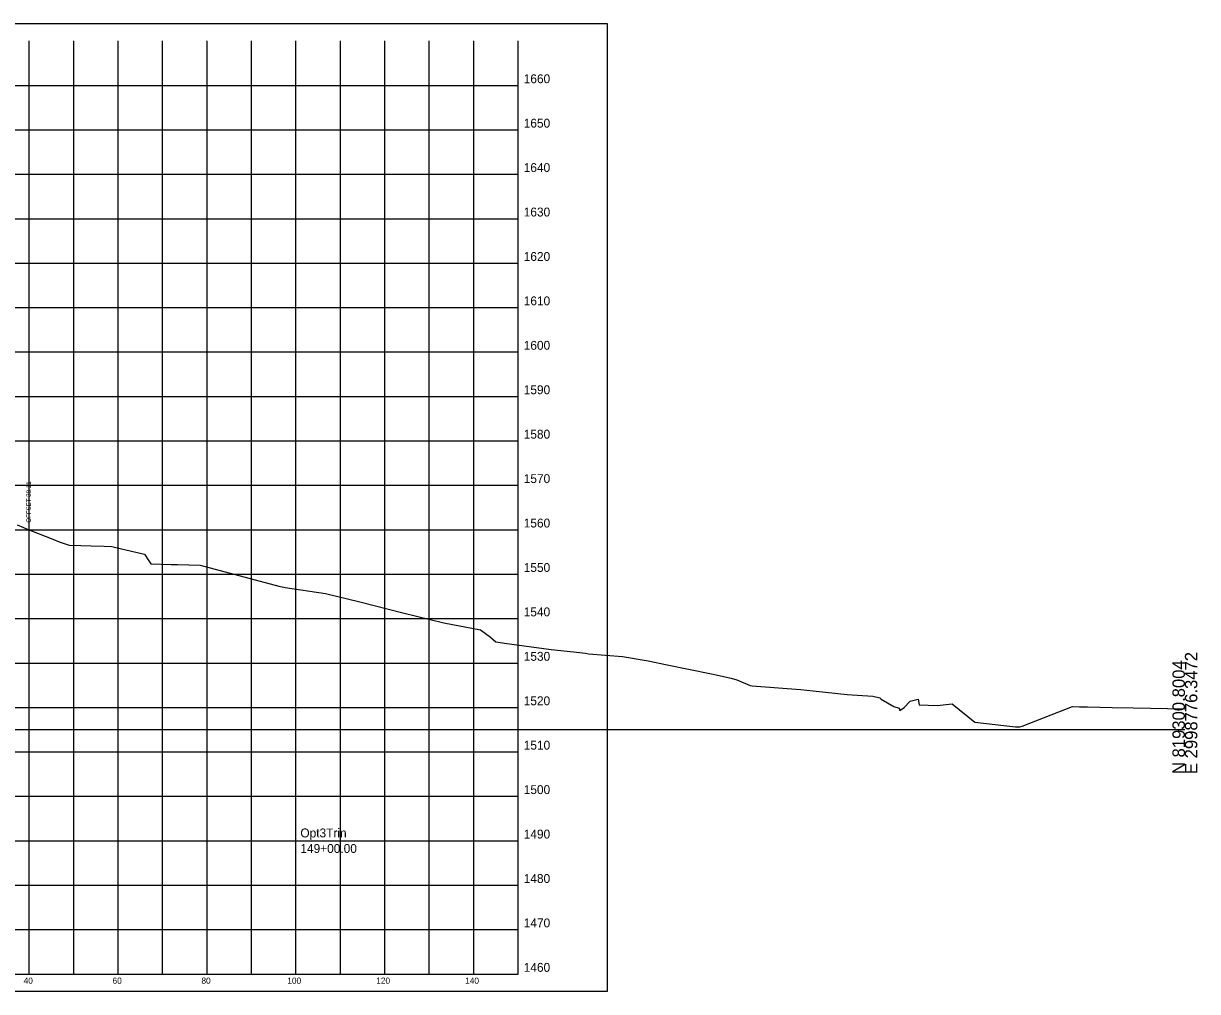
# Model space of a CAD drawing. Extents: x -26 to 603, y -10 to 4805.
# Drawn here: x 338.7 to 602.8, y 3437.1 to 3654.9 of the extents above; entities that cross this region are included whole.
import ezdxf

# ---------------------------------------------------------------- set-up
doc = ezdxf.new("R2010")
doc.units = 0
for name, color, linetype in [('DESIGN - SHEET - Corner Text', 7, 'Continuous'), ('DESIGN - SHEET - Light Grid', 7, 'Continuous'), ('DESIGN - SHEET - Linework', 7, 'Continuous'), ('DESIGN - SHEET - Plot Shape', 7, 'Continuous'), ('DESIGN - TYPICAL - Slope Tie Text', 7, 'Continuous'), ('DESIGN - TYPICAL - Warning Text', 7, 'Continuous'), ('SURVEY - GROUND - Top of Ground', 7, 'Continuous')]:
    doc.layers.add(name, color=color, linetype=linetype)

msp = doc.modelspace()

# ---------------------------------------------------------------- linework, layer by layer
at = {"layer": 'DESIGN - SHEET - Light Grid'}
msp.add_line((300, 3496), (600, 3496), dxfattribs=at)
at = {"layer": 'DESIGN - SHEET - Linework'}
for p, q in [((340, 3441), (340, 3651)), ((350, 3441), (350, 3651)), ((360, 3441), (360, 3651)), ((370, 3441), (370, 3651)), ((380, 3441), (380, 3651)), ((390, 3441), (390, 3651)), ((400, 3441), (400, 3651)), ((410, 3441), (410, 3651)), ((420, 3441), (420, 3651)), ((430, 3441), (430, 3651)), ((440, 3441), (440, 3651)), ((150, 3641), (450, 3641)), ((150, 3631), (450, 3631)), ((150, 3621), (450, 3621)), ((150, 3611), (450, 3611)), ((150, 3601), (450, 3601)), ((150, 3591), (450, 3591)), ((150, 3581), (450, 3581)), ((150, 3571), (450, 3571)), ((150, 3561), (450, 3561)), ((150, 3551), (450, 3551)), ((150, 3541), (450, 3541)), ((150, 3531), (450, 3531)), ((150, 3521), (450, 3521)), ((150, 3511), (450, 3511)), ((150, 3501), (450, 3501)), ((150, 3491), (450, 3491)), ((150, 3481), (450, 3481)), ((150, 3471), (450, 3471)), ((150, 3461), (450, 3461)), ((150, 3451), (450, 3451))]:
    msp.add_line(p, q, dxfattribs=at)
msp.add_lwpolyline([(150, 3651), (150, 3441), (450, 3441), (450, 3651)], dxfattribs=at)
at = {"layer": 'DESIGN - SHEET - Plot Shape'}
msp.add_lwpolyline([(130, 3654.94), (470, 3654.94), (470, 3437.06), (130, 3437.06)], close=True, dxfattribs=at)
at = {"layer": 'SURVEY - GROUND - Top of Ground'}
msp.add_lwpolyline([(337.31, 3542.13), (340.16, 3540.9), (345.29, 3538.84), (346.74, 3538.3), (347.6, 3538.01), (349.01, 3537.55), (351.62, 3537.43), (353.91, 3537.37), (356.82, 3537.3), (358.55, 3537.2), (359.49, 3537), (363.95, 3535.98), (365.94, 3535.53), (366.94, 3534), (367.34, 3533.31), (371.93, 3533.19), (373.37, 3533.16), (378.47, 3532.99), (396.19, 3528.31), (397.29, 3528.04), (397.6, 3527.98), (406.69, 3526.65), (414.4, 3524.78), (424.05, 3522.3), (433.3, 3520.06), (441.5, 3518.46), (443.77, 3516.83), (444.96, 3515.79), (446.49, 3515.52), (446.95, 3515.45), (457.44, 3514.07), (463.9, 3513.39), (464.44, 3513.31), (465.12, 3513.2), (465.82, 3513.07), (473.47, 3512.44), (479.23, 3511.46), (479.62, 3511.39), (483.16, 3510.7), (493.46, 3508.54), (497.91, 3507.62), (499.19, 3507.24), (502.19, 3505.95), (502.66, 3505.84), (513.55, 3505.02), (516.37, 3504.72), (524, 3503.93), (529.79, 3503.54), (531.35, 3503.16), (531.66, 3502.88), (534.55, 3501.2), (535.73, 3500.8), (535.88, 3500.31), (536.85, 3500.99), (538.18, 3502.41), (540, 3502.89), (540.24, 3501.59), (544.28, 3501.46), (547.61, 3501.79), (552.73, 3497.66), (561.91, 3496.63), (562.84, 3496.61), (563.38, 3496.81), (574.68, 3501.2), (576.28, 3501.15), (578.12, 3501.11), (583.67, 3501), (588.37, 3500.88), (599.96, 3500.66), (600, 3500.66)], dxfattribs=at)

# ---------------------------------------------------------------- texts
at = {"layer": 'DESIGN - SHEET - Corner Text'}
for s, height, p in [('1660', 2, (451.25, 3641.5)), ('1650', 2, (451.25, 3631.5)), ('1640', 2, (451.25, 3621.5)), ('1630', 2, (451.25, 3611.5)), ('1620', 2, (451.25, 3601.5)), ('1610', 2, (451.25, 3591.5)), ('1600', 2, (451.25, 3581.5)), ('1590', 2, (451.25, 3571.5)), ('1580', 2, (451.25, 3561.5)), ('1570', 2, (451.25, 3551.5)), ('1560', 2, (451.25, 3541.5)), ('1550', 2, (451.25, 3531.5)), ('1540', 2, (451.25, 3521.5)), ('1530', 2, (451.25, 3511.5)), ('1520', 2, (451.25, 3501.5)), ('1510', 2, (451.25, 3491.5)), ('1500', 2, (451.25, 3481.5)), ('1490', 2, (451.25, 3471.5)), ('1480', 2, (451.25, 3461.5)), ('1470', 2, (451.25, 3451.5)), ('1460', 2, (451.25, 3441.5)), ('40', 1.4, (338.74, 3438.8)), ('60', 1.4, (358.74, 3438.8)), ('80', 1.4, (378.74, 3438.8)), ('100', 1.4, (398.06, 3438.8)), ('120', 1.4, (418.06, 3438.8)), ('140', 1.4, (438.06, 3438.8))]:
    msp.add_text(s, height=height, dxfattribs=at).set_placement(p)
at = {"layer": 'DESIGN - SHEET - Light Grid'}
for s, p in [('E 2998776.3472', (602.8, 3486)), ('N 819300.8004', (600, 3486))]:
    msp.add_text(s, height=2.8, rotation=90, dxfattribs=at).set_placement(p)
at = {"layer": 'DESIGN - TYPICAL - Slope Tie Text'}
msp.add_text('OFFSET 38.11', height=1, rotation=90, dxfattribs=at).set_placement((340.36, 3542.57))
at = {"layer": 'DESIGN - TYPICAL - Warning Text'}
for s, p in [('Opt3Trin', (401, 3471.75)), ('149+00.00', (401, 3468.25))]:
    msp.add_text(s, height=2, dxfattribs=at).set_placement(p)

doc.saveas('drawing.dxf')
